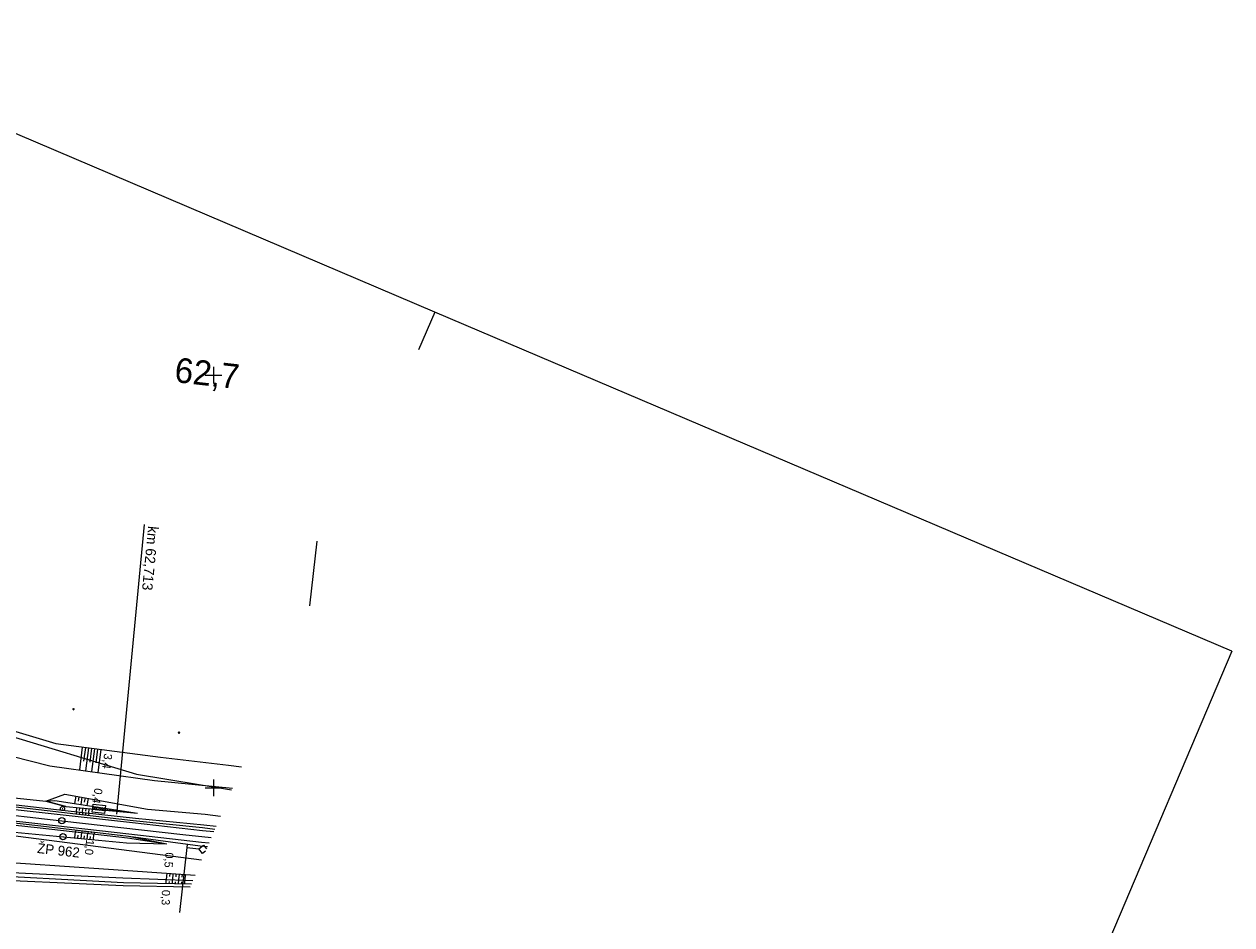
# Model space of a CAD drawing. Extents: x -805636 to -804553, y -1165340 to -1164656.
# Drawn here: x -804845.9 to -804553.1, y -1165133.2 to -1164914.9 of the extents above; entities that cross this region are included whole.
import ezdxf

# ---------------------------------------------------------------- set-up
doc = ezdxf.new("R2010")
doc.units = 0
for name, color, linetype in [('0381KM061-064P - Vrstva 1', 7, 'Continuous'), ('0381KM061-064P - Vrstva 4', 7, 'Continuous'), ('0381KM061-064P - Vrstva 48', 7, 'Continuous'), ('0381KM061-064P - Vrstva 49', 7, 'Continuous'), ('0381KM061-064P - Vrstva 51', 7, 'Continuous'), ('0381KM061-064P - Vrstva 7', 7, 'Continuous'), ('0381KM061-064P - Vrstva 8', 7, 'Continuous'), ('formát', 7, 'Continuous'), ('hran DP - hran DP', 7, 'Continuous'), ('krizky_1000 - Vrstva 1', 7, 'Continuous'), ('vyt_sit - stávající', 7, 'Continuous')]:
    doc.layers.add(name, color=color, linetype=linetype)

msp = doc.modelspace()

# ---------------------------------------------------------------- linework, layer by layer
at = {"layer": '0381KM061-064P - Vrstva 1'}
msp.add_lwpolyline([(-804885.13, -1165102.52), (-804856.51, -1165105.73), (-804836.78, -1165107.96), (-804807.43, -1165111.28), (-804800.55, -1165112.05)], dxfattribs=at)
at = {"layer": '0381KM061-064P - Vrstva 4'}
for points in [[(-804892.37, -1165100.24), (-804859.84, -1165103.98), (-804840.8, -1165106.06), (-804819.65, -1165108.38), (-804802.7, -1165110.3), (-804799.92, -1165110.56)], [(-804892.28, -1165099.85), (-804859.81, -1165103.25), (-804840.34, -1165105.46), (-804819.52, -1165107.92), (-804802.69, -1165109.64), (-804799.68, -1165110)], [(-804892.24, -1165103.28), (-804860.33, -1165106.74), (-804841.86, -1165108.69), (-804820.53, -1165111.13), (-804802.92, -1165113.13), (-804801.1, -1165113.34)], [(-804892.22, -1165103.81), (-804860.51, -1165107.09), (-804841.9, -1165109.22), (-804820.58, -1165111.74), (-804803.21, -1165114.08), (-804801.49, -1165114.25)]]:
    msp.add_lwpolyline(points, dxfattribs=at)
at = {"layer": '0381KM061-064P - Vrstva 48'}
for p, q in [((-804832.45, -1165095.65), (-804831.74, -1165090.13)), ((-804831.42, -1165093.54), (-804831, -1165090.23)), ((-804830.97, -1165095.86), (-804830.25, -1165090.32)), ((-804829.94, -1165093.74), (-804829.51, -1165090.42)), ((-804829.48, -1165096.06), (-804828.77, -1165090.52)), ((-804828.45, -1165093.95), (-804828.02, -1165090.61)), ((-804827.99, -1165096.27), (-804827.28, -1165090.71)), ((-804833.61, -1165103.81), (-804833.29, -1165102.02)), ((-804832.74, -1165103.22), (-804832.55, -1165102.15)), ((-804832.13, -1165104.04), (-804831.81, -1165102.29)), ((-804831.26, -1165103.46), (-804831.07, -1165102.42)), ((-804830.65, -1165104.27), (-804830.33, -1165102.56)), ((-804833.23, -1165105.8), (-804833.29, -1165106.29)), ((-804833.24, -1165105.79), (-804833.15, -1165104.77)), ((-804832.51, -1165106.08), (-804832.54, -1165106.38)), ((-804832.46, -1165105.46), (-804832.4, -1165104.84)), ((-804831.74, -1165105.96), (-804831.8, -1165106.47)), ((-804831.75, -1165105.96), (-804831.66, -1165104.91)), ((-804831.02, -1165106.25), (-804831.05, -1165106.55)), ((-804830.97, -1165105.61), (-804830.91, -1165104.98)), ((-804830.25, -1165106.12), (-804830.31, -1165106.64)), ((-804830.26, -1165106.12), (-804830.16, -1165105.05)), ((-804833.61, -1165112.12), (-804833.46, -1165110.65)), ((-804833.4, -1165110.23), (-804833.45, -1165110.65)), ((-804832.86, -1165112.2), (-804832.79, -1165111.47)), ((-804832.66, -1165110.31), (-804832.68, -1165110.53)), ((-804832.11, -1165112.27), (-804831.97, -1165110.82)), ((-804831.91, -1165110.4), (-804831.96, -1165110.82)), ((-804831.37, -1165112.34), (-804831.3, -1165111.62)), ((-804831.17, -1165110.49), (-804831.19, -1165110.7)), ((-804830.62, -1165112.41), (-804830.48, -1165111)), ((-804830.42, -1165110.58), (-804830.47, -1165111)), ((-804829.87, -1165112.48), (-804829.81, -1165111.78)), ((-804829.68, -1165110.67), (-804829.7, -1165110.87)), ((-804829.13, -1165112.56), (-804828.99, -1165111.17)), ((-804828.93, -1165110.75), (-804828.98, -1165111.17)), ((-804811.36, -1165120.67), (-804811.46, -1165122.21)), ((-804810.61, -1165120.72), (-804810.66, -1165121.48)), ((-804809.86, -1165120.78), (-804809.96, -1165122.27)), ((-804809.11, -1165120.83), (-804809.16, -1165121.56)), ((-804808.36, -1165120.88), (-804808.46, -1165122.33)), ((-804807.62, -1165120.93), (-804807.67, -1165121.65)), ((-804806.87, -1165120.98), (-804806.97, -1165122.39)), ((-804811.47, -1165123.14), (-804811.45, -1165122.21)), ((-804810.72, -1165123.15), (-804810.71, -1165122.7)), ((-804809.97, -1165123.17), (-804809.95, -1165122.27)), ((-804809.22, -1165123.19), (-804809.21, -1165122.74)), ((-804808.47, -1165123.2), (-804808.45, -1165122.33)), ((-804807.72, -1165123.22), (-804807.71, -1165122.79)), ((-804806.97, -1165123.24), (-804806.95, -1165122.39))]:
    msp.add_line(p, q, dxfattribs=at)
at = {"layer": '0381KM061-064P - Vrstva 49'}
for p, q in [((-804833.78, -1165081.15), (-804834.13, -1165080.8)), ((-804833.78, -1165080.8), (-804834.13, -1165081.15)), ((-804808.18, -1165086.83), (-804808.54, -1165086.48)), ((-804808.18, -1165086.48), (-804808.54, -1165086.83))]:
    msp.add_line(p, q, dxfattribs=at)
for points in [[(-805084.74, -1165039.06), (-805061.55, -1165052.74), (-805034.17, -1165068.7), (-805016.31, -1165078.58), (-804984.31, -1165094.26), (-804952.92, -1165105.84), (-804923.4, -1165113.55), (-804890.69, -1165118.62), (-804860.79, -1165119.97), (-804821.99, -1165121.8), (-804804.98, -1165122.47)], [(-805085.43, -1165039.91), (-805061.8, -1165053.37), (-805034.45, -1165069.27), (-805016.82, -1165079.3), (-804984.87, -1165094.97), (-804952.63, -1165107.29), (-804923.66, -1165115.02), (-804890.91, -1165119.51), (-804860.93, -1165120.87), (-804821.85, -1165122.9), (-804805.33, -1165123.27)], [(-805060.73, -1165049.17), (-805047.98, -1165055.77), (-805031.23, -1165064.28), (-805013.07, -1165072.73), (-804991.62, -1165081.24), (-804976.47, -1165086.37), (-804956.64, -1165091.96), (-804934.05, -1165097.54), (-804913.13, -1165101.06), (-804892.22, -1165103.81), (-804860.51, -1165107.09), (-804841.9, -1165109.22), (-804820.58, -1165111.74), (-804811.31, -1165113.56)], [(-805033.41, -1165066.35), (-805014.98, -1165076.25), (-804982.53, -1165092.31), (-804953.12, -1165104.6), (-804922.96, -1165111.59), (-804890.43, -1165117.32), (-804859.92, -1165117.39), (-804821.94, -1165119.94), (-804804.42, -1165121.15)], [(-805010.72, -1165069.47), (-804990.45, -1165077.48), (-804974.57, -1165082.73), (-804955.28, -1165088.2), (-804932.96, -1165093.51), (-804912.39, -1165097.1), (-804892.28, -1165099.85), (-804859.81, -1165103.25), (-804840.34, -1165105.46), (-804819.52, -1165107.92), (-804802.69, -1165109.64), (-804799.68, -1165110)], [(-804994.86, -1165072.51), (-804973.16, -1165079.86), (-804954.29, -1165084.75), (-804932.5, -1165089.79), (-804920.22, -1165090.5), (-804911.77, -1165084.22), (-804893.29, -1165083.05), (-804876.57, -1165085.04), (-804853.44, -1165091.21), (-804839.72, -1165094.63), (-804814.35, -1165098.18)], [(-804930.03, -1165080.86), (-804917.17, -1165078.41), (-804896.14, -1165076.16), (-804872.64, -1165078.3), (-804857.5, -1165083.55), (-804838.27, -1165089.29), (-804812.85, -1165092.56), (-804796.39, -1165094.52), (-804793.24, -1165094.87)], [(-804892.03, -1165097.79), (-804859.05, -1165101.29), (-804840.64, -1165103.22)], [(-804892.31, -1165098.96), (-804859.08, -1165102.8), (-804835.93, -1165105.5), (-804818.93, -1165107.36), (-804802.32, -1165108.93), (-804799.37, -1165109.27)], [(-804814.35, -1165098.18), (-804795.44, -1165100.05)], [(-804840.64, -1165103.22), (-804836.05, -1165101.51), (-804816.03, -1165105.18), (-804802.02, -1165106.41), (-804798.34, -1165106.84)], [(-804840.64, -1165103.22), (-804838.47, -1165103.07), (-804818.4, -1165106.14)], [(-804840.64, -1165103.22), (-804835.82, -1165104.53), (-804840.64, -1165103.22), (-804835.82, -1165104.53), (-804818.4, -1165106.14)], [(-804892.44, -1165105.41), (-804859.96, -1165109.29), (-804851.61, -1165110.39), (-804821.13, -1165113.33), (-804811.31, -1165113.56)], [(-804892.37, -1165104.14), (-804860.79, -1165107.69), (-804842.05, -1165109.66), (-804820.85, -1165112.11), (-804811.31, -1165113.56)]]:
    msp.add_lwpolyline(points, dxfattribs=at)
at = {"layer": '0381KM061-064P - Vrstva 51'}
msp.add_lwpolyline([(-805085.93, -1165040.55), (-805062.08, -1165054.12), (-805034.69, -1165069.73), (-805017.21, -1165079.65), (-804985.71, -1165095.39), (-804952.66, -1165107.75), (-804923.93, -1165115.31), (-804890.75, -1165120.1), (-804861.18, -1165121.85), (-804821.92, -1165123.67), (-804805.64, -1165124)], dxfattribs=at)
at = {"layer": '0381KM061-064P - Vrstva 7'}
msp.add_line((-804836.67, -1165105.01), (-804836.57, -1165105.03), dxfattribs=at)
for centre, radius in [((-804836.62, -1165105.02), 0.5), ((-804836.78, -1165107.96), 0.75)]:
    msp.add_circle(centre, radius, dxfattribs=at)
at = {"layer": '0381KM061-064P - Vrstva 8'}
for p, q in [((-804823.36, -1165105.59), (-804816.74, -1165036.14)), ((-804776.65, -1165055.87), (-804774.89, -1165040.2)), ((-804829.06, -1165104.6), (-804829.31, -1165104.79)), ((-804828.53, -1165104.66), (-804829.3, -1165105.27)), ((-804828.01, -1165104.72), (-804828.78, -1165105.33)), ((-804827.48, -1165104.77), (-804828.25, -1165105.39)), ((-804826.95, -1165104.83), (-804827.72, -1165105.45)), ((-804826.42, -1165104.89), (-804827.2, -1165105.51)), ((-804826.35, -1165105.31), (-804826.67, -1165105.57)), ((-804823.44, -1165106.34), (-804823.28, -1165104.85)), ((-804806.51, -1165114.46), (-804808.28, -1165130.22)), ((-804806.43, -1165113.71), (-804806.59, -1165115.21))]:
    msp.add_line(p, q, dxfattribs=at)
for points in [[(-804826.45, -1165106.25), (-804829.43, -1165105.91), (-804829.21, -1165103.92), (-804826.23, -1165104.26), (-804826.45, -1165106.25)], [(-804826.34, -1165105.26), (-804823.36, -1165105.59)], [(-804806.51, -1165114.46), (-804803.53, -1165114.8), (-804802.42, -1165113.91), (-804801.72, -1165114.8)], [(-804801.95, -1165115.35), (-804802.65, -1165115.9), (-804803.53, -1165114.8)]]:
    msp.add_lwpolyline(points, dxfattribs=at)
msp.add_lwpolyline([(-804826.38, -1165105.6), (-804829.36, -1165105.26), (-804829.28, -1165104.57), (-804826.3, -1165104.91)], close=True, dxfattribs=at)
at = {"layer": 'formát'}
for p, q in [((-804746.36, -1164984.69), (-804939.6, -1164902.47)), ((-804746.36, -1164984.69), (-804750.28, -1164993.89)), ((-804553.13, -1165066.91), (-804746.36, -1164984.69)), ((-804553.13, -1165066.91), (-804669.4, -1165340.2))]:
    msp.add_line(p, q, dxfattribs=at)
at = {"layer": 'hran DP - hran DP'}
for p, q in [((-804851.84, -1165086.69), (-804818.68, -1165096.66)), ((-804818.68, -1165096.66), (-804795.63, -1165100.48)), ((-804802.89, -1165117.55), (-804934.32, -1165100.62))]:
    msp.add_line(p, q, dxfattribs=at)
at = {"layer": 'krizky_1000 - Vrstva 1'}
for points in [[(-804800, -1164998), (-804800, -1165002)], [(-804802, -1165000), (-804798, -1165000)], [(-804800, -1165098), (-804800, -1165102)], [(-804802, -1165100), (-804798, -1165100)]]:
    msp.add_lwpolyline(points, dxfattribs=at)
at = {"layer": 'vyt_sit - stávající'}
msp.add_line((-804836.57, -1165111.8), (-804836.48, -1165111.85), dxfattribs=at)
msp.add_circle((-804836.52, -1165111.83), 0.756, dxfattribs=at)

# ---------------------------------------------------------------- texts
at = {"layer": '0381KM061-064P - Vrstva 48'}
for s, rotation, p in [('3,4', 262.6656, (-804826.51, -1165091.58)), ('0,4', 259.6289, (-804828.81, -1165099.95)), ('1,0', 264.4873, (-804830.87, -1165112.47)), ('0,5', 266.024, (-804811.67, -1165115.58)), ('0,3', 268.6994, (-804812.52, -1165124.7))]:
    msp.add_text(s, height=2, rotation=rotation, dxfattribs=at).set_placement(p)
at = {"layer": '0381KM061-064P - Vrstva 7'}
msp.add_text('62,7', height=6, rotation=353.5516, dxfattribs=at).set_placement((-804809.66, -1165001.63))
at = {"layer": '0381KM061-064P - Vrstva 8'}
msp.add_text('km 62,713', height=2.5, rotation=264.5581, dxfattribs=at).set_placement((-804815.85, -1165036.49))
at = {"layer": 'vyt_sit - stávající'}
msp.add_text('ŽP 962', height=2.4, rotation=353.5611, dxfattribs=at).set_placement((-804842.86, -1165115.77))

doc.saveas('drawing.dxf')
